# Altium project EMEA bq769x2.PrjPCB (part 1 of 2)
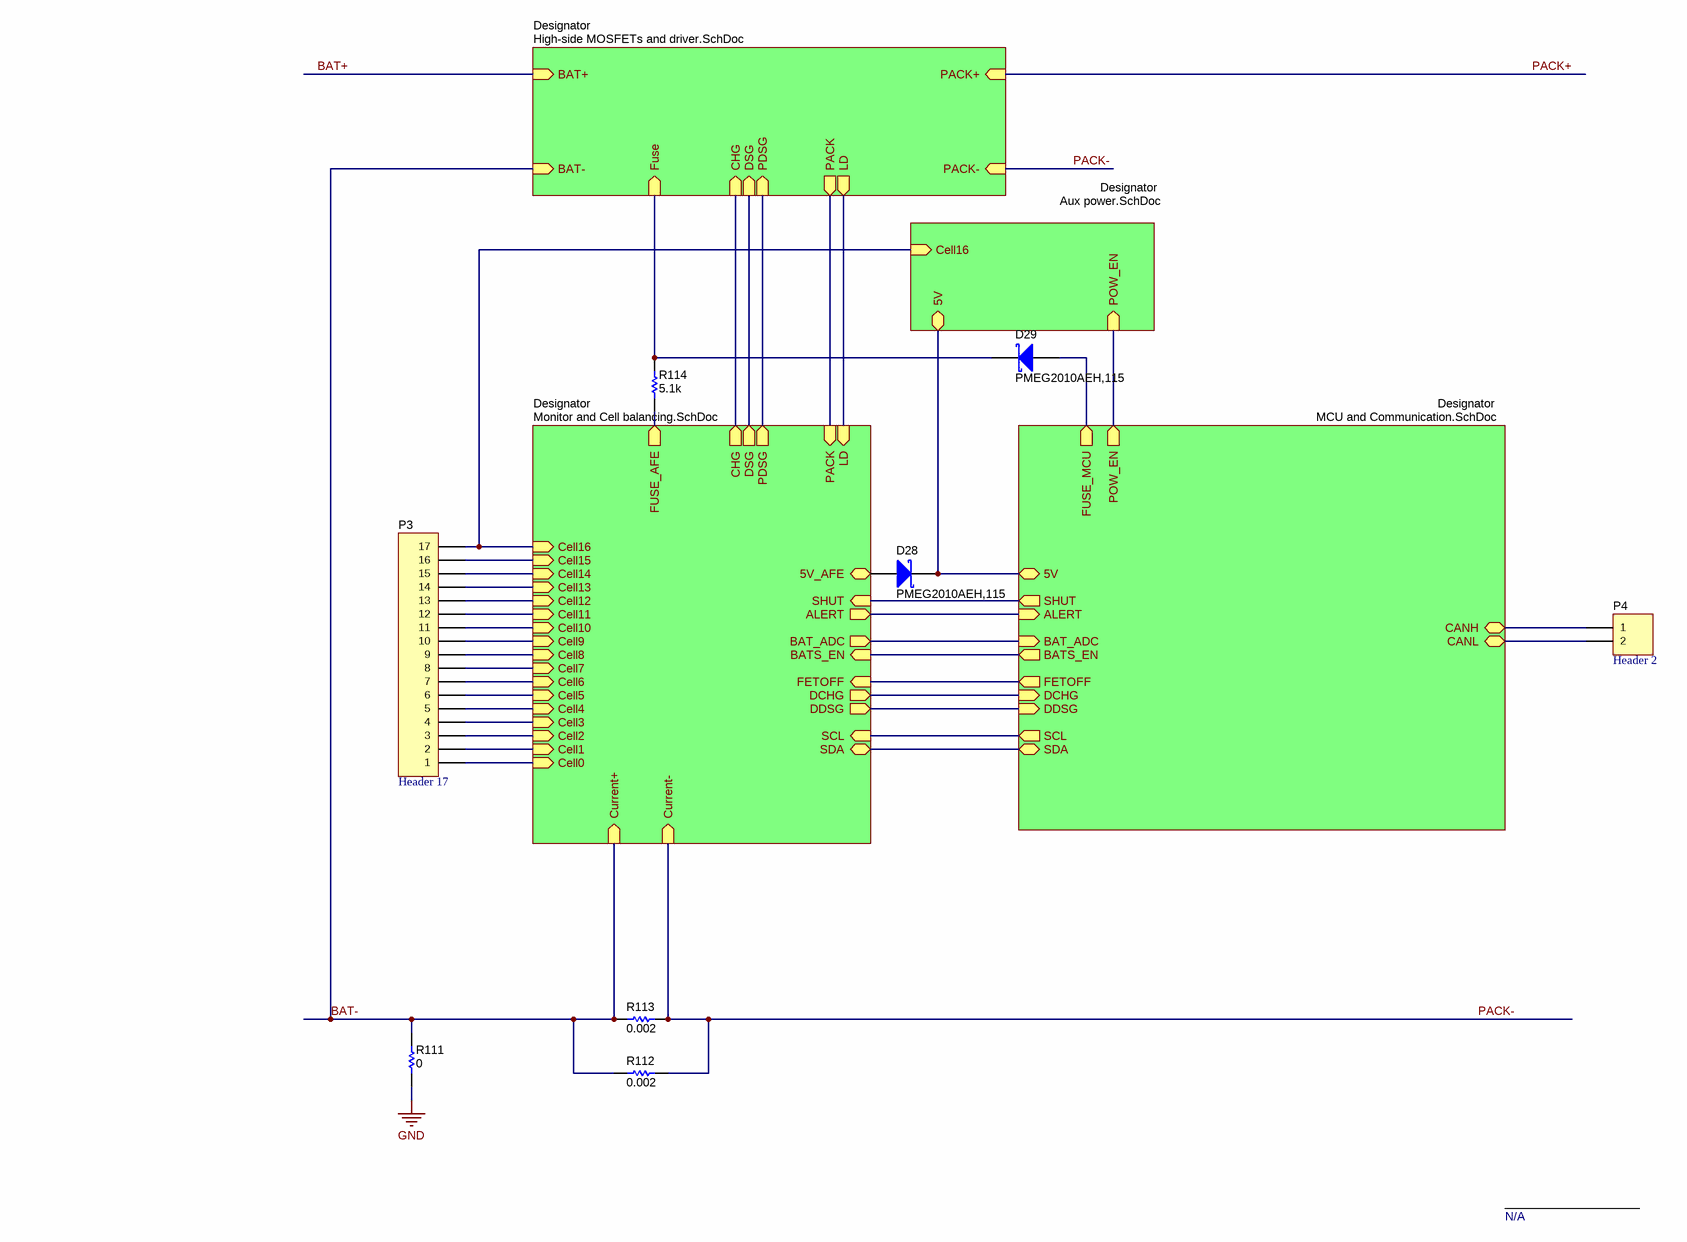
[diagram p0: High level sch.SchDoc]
TID: TIDA-010208; TechSupport: http://www.ti.com/support; SCH_Rev: E1; PRJ_Title: 10s-16s Battery Pack reference design; PRJ_Number: TIDA-010208; PRJ_Engineer: Ryan Tan; PRJ_Customer: Public Release; PCB_Rev: E1; PCB_Layout: Ryan Tan; CopyrightYear: 2017
7 sheets, 308 parts. Net scope: hierarchical (ports join the sheet entries above them; power ports are global).
Board file: v1.PcbDoc
Sheets:
  High level sch.SchDoc
    Designator = Monitor and Cell balancing.SchDoc
    Designator = Aux power.SchDoc
    Designator = MCU and Communication.SchDoc
    Designator = High-side MOSFETs and driver.SchDoc
    Designator = EVM_Hardware.SchDoc
    Designator = CoverSheet.SchDoc

## Sheet High level sch.SchDoc
size 431 x 279 mm; Date: Not shown in title block; ApprovedBy: Not shown in title block; CheckedBy: Not shown in title block; Author: Not shown in title block; CompanyName: Not shown in title block; Engineer: Not shown in title block; Organization: Not shown in title block; Address1: Not shown in title block; Address2: Not shown in title block; Address3: Not shown in title block; Address4: Not shown in title block; DocumentNumber: 1; Revision: Use project parameter SCH_Rev; SheetNumber: 2; SheetTotal: 7; PageSetup: Record=PageOptions¦CenterHorizontal=True¦CenterVertical=True¦PrintScale=1.00¦XCorrection=1.00¦YCorrection=1.00¦PrintKind=0¦BorderSize=5000000¦LeftOffset=0¦BottomOffset=0¦Orientation=2¦PaperLength=1000¦PaperWidth=1000¦Scale=100¦PaperSource=15¦PrintQuality=600¦MediaType=1¦DitherType=10¦PaperKind=Letter¦PrintScaleMode=1

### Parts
D28  PMEG2010AEH,115  [SOD-123F]
D29  PMEG2010AEH,115  [SOD-123F]
P3  Header 17  [HDR1X17]
P4  Header 2  [HDR1X2]
R111  ValueDisplayed: 0  [0603]  (hidden comment: CRCW06030000Z0EA)
R112  ValueDisplayed: 0.002  [2512]  (hidden comment: CSNL2512FT2L00)
R113  ValueDisplayed: 0.002  [2512]  (hidden comment: CSNL2512FT2L00)
R114  ValueDisplayed: 5.1k  [0603]  (hidden comment: CRCW06035K10JNEA)

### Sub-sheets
Designator = Monitor and Cell balancing.SchDoc: SHUT (in), ALERT (out), DDSG (out), DSG (out), DCHG (out), SCL (in), PDSG (out), Cell9 (in), SDA (bidir), CHG (out), Cell4 (in), Cell3 (in), Cell5 (in), Current+ (in), Current- (in), Cell8 (in), Cell12 (in), Cell6 (in), Cell7 (in), Cell10 (in), Cell11 (in), Cell2 (in), Cell1 (in), Cell15 (in), Cell16 (in), Cell0 (in), Cell13 (in), Cell14 (in), FETOFF (in), PACK (in), LD (in), 5V_AFE, FUSE_AFE (out), BAT_ADC (out), BATS_EN (in)
Designator = Aux power.SchDoc: POW_EN (in), 5V, Cell16 (in)
Designator = MCU and Communication.SchDoc: SDA (bidir), SCL (out), CANL (bidir), CANH (bidir), ALERT (in), POW_EN (out), DDSG (in), DCHG (in), SHUT (out), FETOFF (out), 5V, FUSE_MCU (out), BAT_ADC (in), BATS_EN (out)
Designator = High-side MOSFETs and driver.SchDoc: PACK- (in), CHG (in), DSG (in), Fuse (in), PACK+ (in), BAT+ (in), PACK (out), LD (out), PDSG (in), BAT- (in)
Designator = EVM_Hardware.SchDoc: no entries
Designator = CoverSheet.SchDoc: no entries

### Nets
GND: R111.1
5V: D28.1(K) ; sheet Designator/5V, sheet Designator/5V
5V_AFE: D28.2(A) ; sheet Designator/5V_AFE
ALERT: sheet Designator/ALERT, sheet Designator/ALERT
BAT-: R111.2 R112.1 R113.1 ; sheet Designator/Current+, sheet Designator/BAT-
BAT_ADC: sheet Designator/BAT_ADC, sheet Designator/BAT_ADC
BATS_EN: sheet Designator/BATS_EN, sheet Designator/BATS_EN
CANH: P4.1 ; sheet Designator/CANH
CANL: P4.2 ; sheet Designator/CANL
Cell0: P3.1 ; sheet Designator/Cell0
Cell1: P3.2 ; sheet Designator/Cell1
Cell2: P3.3 ; sheet Designator/Cell2
Cell3: P3.4 ; sheet Designator/Cell3
Cell4: P3.5 ; sheet Designator/Cell4
Cell5: P3.6 ; sheet Designator/Cell5
Cell6: P3.7 ; sheet Designator/Cell6
Cell7: P3.8 ; sheet Designator/Cell7
Cell8: P3.9 ; sheet Designator/Cell8
Cell9: P3.10 ; sheet Designator/Cell9
Cell10: P3.11 ; sheet Designator/Cell10
Cell11: P3.12 ; sheet Designator/Cell11
Cell12: P3.13 ; sheet Designator/Cell12
Cell13: P3.14 ; sheet Designator/Cell13
Cell14: P3.15 ; sheet Designator/Cell14
Cell15: P3.16 ; sheet Designator/Cell15
Cell16: P3.17 ; sheet Designator/Cell16, sheet Designator/Cell16
CHG: sheet Designator/CHG, sheet Designator/CHG
DCHG: sheet Designator/DCHG, sheet Designator/DCHG
DDSG: sheet Designator/DDSG, sheet Designator/DDSG
DSG: sheet Designator/DSG, sheet Designator/DSG
FETOFF: sheet Designator/FETOFF, sheet Designator/FETOFF
Fuse: D29.1(K) R114.2 ; sheet Designator/Fuse
FUSE_AFE: R114.1 ; sheet Designator/FUSE_AFE
FUSE_MCU: D29.2(A) ; sheet Designator/FUSE_MCU
LD: sheet Designator/LD, sheet Designator/LD
PACK: sheet Designator/PACK, sheet Designator/PACK
PACK-: R112.2 R113.2 ; sheet Designator/Current-, sheet Designator/PACK-
PDSG: sheet Designator/PDSG, sheet Designator/PDSG
POW_EN: sheet Designator/POW_EN, sheet Designator/POW_EN
SCL: sheet Designator/SCL, sheet Designator/SCL
SDA: sheet Designator/SDA, sheet Designator/SDA
SHUT: sheet Designator/SHUT, sheet Designator/SHUT

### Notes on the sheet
- N/A

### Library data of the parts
D28 D29 = PMEG2010AEH,115: Diode, Schottky, 20 V, 1 A, SOD-123F; Manufacturer: Nexperia; U/M: EA; Vf_V: 0.43; Value: 20V; Value1: 1A; Value2: 0.43V; Io_A: 1; Vr_V: 20; TJmax_C: 150; SizeAreaWB_mm2: 11.7; SizeArea_mm2: 5.6; SizeX_mm: 3.5; SizeY_mm: 1.6; SizeZ_mm: 1.1; AEC Category: Q101; Green_Lifecycle: Not Set; Green_REACh: Incomplete
P3 = Header 17: Header, 17-Pin
P4 = Header 2: Header, 2-Pin
R111 = CRCW06030000Z0EA: RES, 0, 5%, 0.1 W, 0603; Manufacturer: Vishay-Dale; CompType: Resistor; Value: 0; Value_Code: 0000; Tolerance_%: 5; Power_W: 0.1; Value2: 0.1W; VDC_V: 75; TempCo: 200 ppm/C; SizeArea_mm2: 1.28; SizeX_mm: 1.6; SizeY_mm: 0.8; SizeZ_mm: 1; EIA_Code: E24; U/M: EA; AEC Category: Q200; Green_Lifecycle: Active; Green_REACh: Passed
R112 R113 = CSNL2512FT2L00: RES, 0.002, 1%, 2 W, 2512; Manufacturer: Stackpole Electronics Inc; CompType: Resistor; Value: 0.002; Value_Code: 2L000; Tolerance_%: 1; Power_W: 2; Value2: 2W; VDC_V: 200; TempCo: 50 ppm/C; SizeArea_mm2: 20.16; SizeX_mm: 6.3; SizeY_mm: 3.2; SizeZ_mm: 0.71; U/M: EA; AEC Category: Q200
R114 = CRCW06035K10JNEA: RES, 5.1 k, 5%, 0.1 W, 0603; Manufacturer: Vishay-Dale; CompType: Resistor; Value: 5.1k; Res_ohm: 5100; Value_Code: 5k10; Tolerance_%: 5; Power_W: 0.1; Value2: 0.1W; VDC_V: 75; TempCo: 200 ppm/C; SizeArea_mm2: 1.28; SizeX_mm: 1.6; SizeY_mm: 0.8; SizeZ_mm: 1; EIA_Code: E24; U/M: EA; AEC Category: Q200; Green_Lifecycle: Active; Green_REACh: Passed

## Sheet Monitor and Cell balancing.SchDoc
size 431 x 279 mm; Date: Not shown in title block; ApprovedBy: Not shown in title block; CheckedBy: Not shown in title block; Author: Not shown in title block; CompanyName: Not shown in title block; Engineer: Not shown in title block; Organization: Not shown in title block; Address1: Not shown in title block; Address2: Not shown in title block; Address3: Not shown in title block; Address4: Not shown in title block; DocumentNumber: 1; Revision: Use project parameter SCH_Rev; SheetNumber: 3; SheetTotal: 7; PageSetup: Record=PageOptions¦CenterHorizontal=True¦CenterVertical=True¦PrintScale=1.00¦XCorrection=1.00¦YCorrection=1.00¦PrintKind=0¦BorderSize=5000000¦LeftOffset=0¦BottomOffset=0¦Orientation=2¦PaperLength=1000¦PaperWidth=1000¦Scale=100¦PaperSource=15¦PrintQuality=600¦MediaType=1¦DitherType=10¦PaperKind=Letter¦PrintScaleMode=1
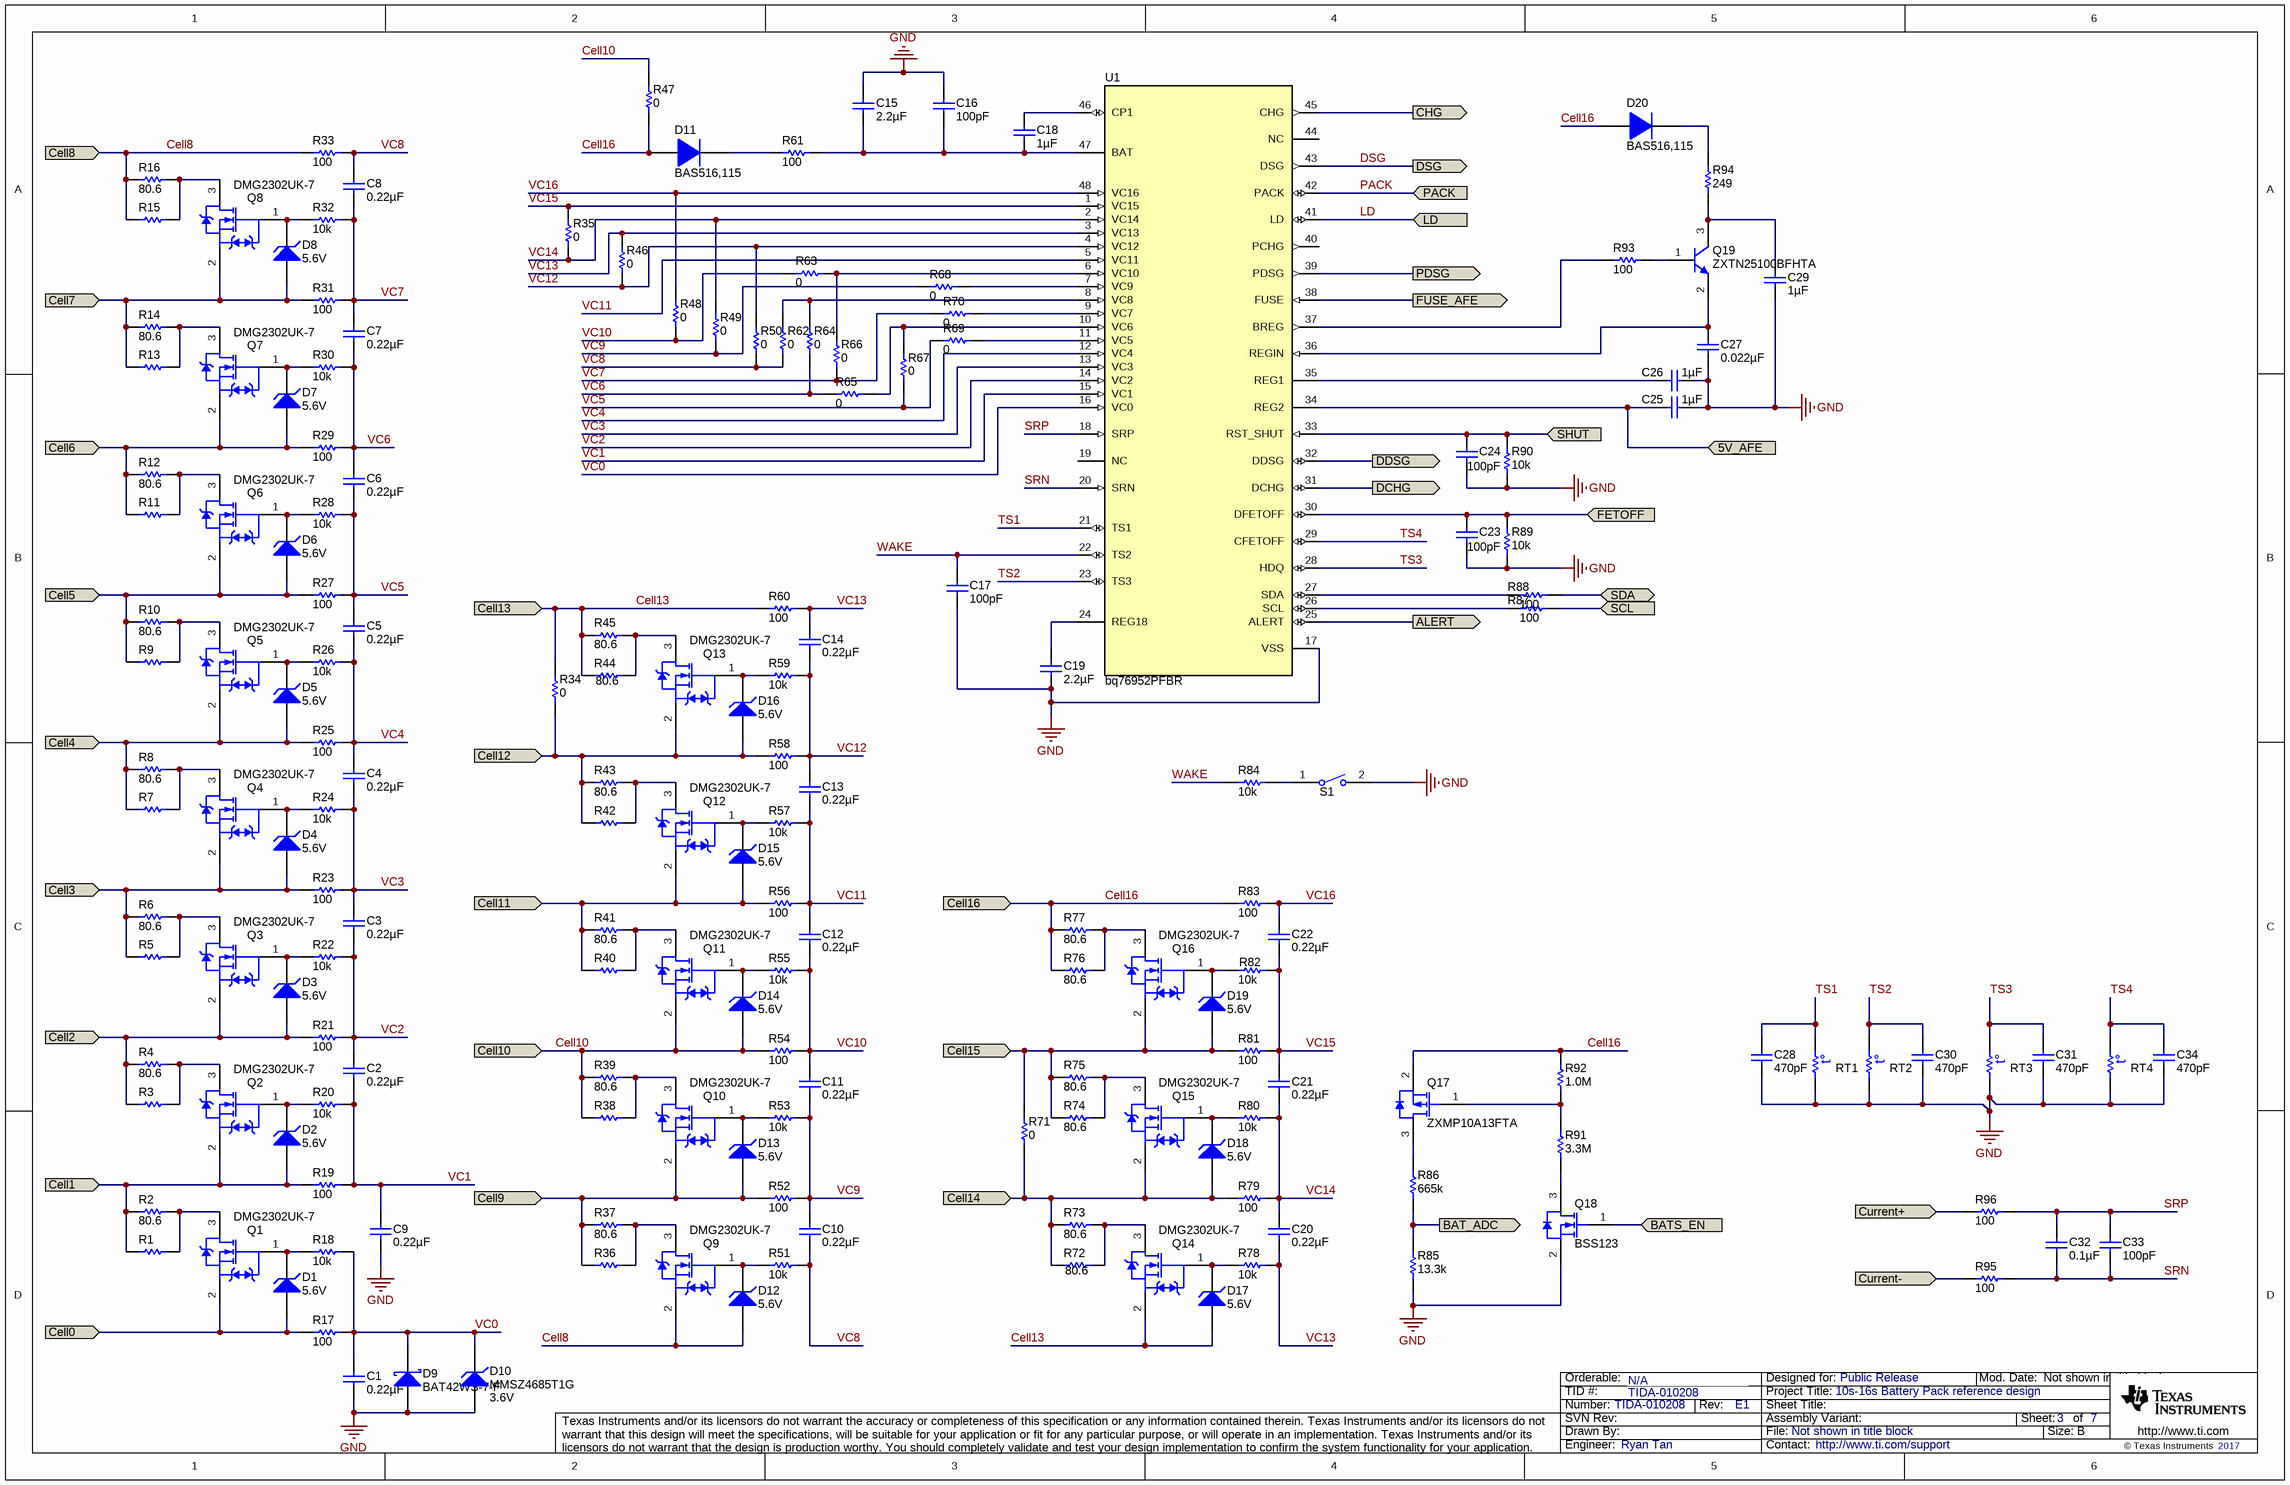
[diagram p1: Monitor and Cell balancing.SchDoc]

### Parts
C1  ValueDisplayed: 0.22µF  [0603]  (hidden comment: GCM188R71H224KA64D)
C2  ValueDisplayed: 0.22µF  [0603]  (hidden comment: GCM188R71H224KA64D)
C3  ValueDisplayed: 0.22µF  [0603]  (hidden comment: GCM188R71H224KA64D)
C4  ValueDisplayed: 0.22µF  [0603]  (hidden comment: GCM188R71H224KA64D)
C5  ValueDisplayed: 0.22µF  [0603]  (hidden comment: GCM188R71H224KA64D)
C6  ValueDisplayed: 0.22µF  [0603]  (hidden comment: GCM188R71H224KA64D)
C7  ValueDisplayed: 0.22µF  [0603]  (hidden comment: GCM188R71H224KA64D)
C8  ValueDisplayed: 0.22µF  [0603]  (hidden comment: GCM188R71H224KA64D)
C9  ValueDisplayed: 0.22µF  [0603]  (hidden comment: GCM188R71H224KA64D)
C10  ValueDisplayed: 0.22µF  [0603]  (hidden comment: GCM188R71H224KA64D)
C11  ValueDisplayed: 0.22µF  [0603]  (hidden comment: GCM188R71H224KA64D)
C12  ValueDisplayed: 0.22µF  [0603]  (hidden comment: GCM188R71H224KA64D)
C13  ValueDisplayed: 0.22µF  [0603]  (hidden comment: GCM188R71H224KA64D)
C14  ValueDisplayed: 0.22µF  [0603]  (hidden comment: GCM188R71H224KA64D)
C15  ValueDisplayed: 2.2µF  [1206_190]  (hidden comment: CL31B225KCHSNNE)
C16  ValueDisplayed: 100pF  [0603]  (hidden comment: GRM1885C2A101JA01D)
C17  ValueDisplayed: 100pF  [0603]  (hidden comment: GRM1885C2A101JA01D)
C18  ValueDisplayed: 1µF  [0603]  (hidden comment: C1608X7R1E105K080AB)
C19  ValueDisplayed: 2.2µF  [0603]  (hidden comment: EMK107BB7225MA-T)
C20  ValueDisplayed: 0.22µF  [0603]  (hidden comment: GCM188R71H224KA64D)
C21  ValueDisplayed: 0.22µF  [0603]  (hidden comment: GCM188R71H224KA64D)
C22  ValueDisplayed: 0.22µF  [0603]  (hidden comment: GCM188R71H224KA64D)
C23  ValueDisplayed: 100pF  [0603]  (hidden comment: GRM1885C2A101JA01D)
C24  ValueDisplayed: 100pF  [0603]  (hidden comment: GRM1885C2A101JA01D)
C25  ValueDisplayed: 1µF  [0603]  (hidden comment: GCM188R71C105KA64D)
C26  ValueDisplayed: 1µF  [0603]  (hidden comment: GCM188R71C105KA64D)
C27  ValueDisplayed: 0.022µF  [0603]  (hidden comment: GRM188R71H223KA01D)
C28  ValueDisplayed: 470pF  [0603]  (hidden comment: GRM188R71H471KA01D)
C29  ValueDisplayed: 1µF  [1206_180]  (hidden comment: C3216X7R2A105K160AA)
C30  ValueDisplayed: 470pF  [0603]  (hidden comment: GRM188R71H471KA01D)
C31  ValueDisplayed: 470pF  [0603]  (hidden comment: GRM188R71H471KA01D)
C32  ValueDisplayed: 0.1µF  [0603]  (hidden comment: GRM188R71H104KA93D)
C33  ValueDisplayed: 100pF  [0603]  (hidden comment: GRM1885C2A101JA01D)
C34  ValueDisplayed: 470pF  [0603]  (hidden comment: GRM188R71H471KA01D)
D1  value 5.6V  [SOD-523]  (hidden comment: BZT52C5V6T-7)
D2  value 5.6V  [SOD-523]  (hidden comment: BZT52C5V6T-7)
D3  value 5.6V  [SOD-523]  (hidden comment: BZT52C5V6T-7)
D4  value 5.6V  [SOD-523]  (hidden comment: BZT52C5V6T-7)
D5  value 5.6V  [SOD-523]  (hidden comment: BZT52C5V6T-7)
D6  value 5.6V  [SOD-523]  (hidden comment: BZT52C5V6T-7)
D7  value 5.6V  [SOD-523]  (hidden comment: BZT52C5V6T-7)
D8  value 5.6V  [SOD-523]  (hidden comment: BZT52C5V6T-7)
D9  BAT42WS-7-F  [SOD-323]
D10  MMSZ4685T1G  value 3.6V  [SOD-123]
D11  BAS516,115  [SOD-523]
D12  value 5.6V  [SOD-523]  (hidden comment: BZT52C5V6T-7)
D13  value 5.6V  [SOD-523]  (hidden comment: BZT52C5V6T-7)
D14  value 5.6V  [SOD-523]  (hidden comment: BZT52C5V6T-7)
D15  value 5.6V  [SOD-523]  (hidden comment: BZT52C5V6T-7)
D16  value 5.6V  [SOD-523]  (hidden comment: BZT52C5V6T-7)
D17  value 5.6V  [SOD-523]  (hidden comment: BZT52C5V6T-7)
D18  value 5.6V  [SOD-523]  (hidden comment: BZT52C5V6T-7)
D19  value 5.6V  [SOD-523]  (hidden comment: BZT52C5V6T-7)
D20  BAS516,115  [SOD-523]
Q1  DMG2302UK-7  [SOT-23]
Q2  DMG2302UK-7  [SOT-23]
Q3  DMG2302UK-7  [SOT-23]
Q4  DMG2302UK-7  [SOT-23]
Q5  DMG2302UK-7  [SOT-23]
Q6  DMG2302UK-7  [SOT-23]
Q7  DMG2302UK-7  [SOT-23]
Q8  DMG2302UK-7  [SOT-23]
Q9  DMG2302UK-7  [SOT-23]
Q10  DMG2302UK-7  [SOT-23]
Q11  DMG2302UK-7  [SOT-23]
Q12  DMG2302UK-7  [SOT-23]
Q13  DMG2302UK-7  [SOT-23]
Q14  DMG2302UK-7  [SOT-23]
Q15  DMG2302UK-7  [SOT-23]
Q16  DMG2302UK-7  [SOT-23]
Q17  ZXMP10A13FTA  [SOT-23]
Q18  BSS123  [SOT-23]
Q19  ZXTN25100BFHTA  [SOT-23]
R1  CRCW120680R6FKEA  [1206]  (value not drawn)
R2  ValueDisplayed: 80.6  [1206]  (hidden comment: CRCW120680R6FKEA)
R3  CRCW120680R6FKEA  [1206]  (value not drawn)
R4  ValueDisplayed: 80.6  [1206]  (hidden comment: CRCW120680R6FKEA)
R5  CRCW120680R6FKEA  [1206]  (value not drawn)
R6  ValueDisplayed: 80.6  [1206]  (hidden comment: CRCW120680R6FKEA)
R7  CRCW120680R6FKEA  [1206]  (value not drawn)
R8  ValueDisplayed: 80.6  [1206]  (hidden comment: CRCW120680R6FKEA)
R9  CRCW120680R6FKEA  [1206]  (value not drawn)
R10  ValueDisplayed: 80.6  [1206]  (hidden comment: CRCW120680R6FKEA)
R11  CRCW120680R6FKEA  [1206]  (value not drawn)
R12  ValueDisplayed: 80.6  [1206]  (hidden comment: CRCW120680R6FKEA)
R13  CRCW120680R6FKEA  [1206]  (value not drawn)
R14  ValueDisplayed: 80.6  [1206]  (hidden comment: CRCW120680R6FKEA)
R15  CRCW120680R6FKEA  [1206]  (value not drawn)
R16  ValueDisplayed: 80.6  [1206]  (hidden comment: CRCW120680R6FKEA)
R17  ValueDisplayed: 100  [0603]  (hidden comment: CRCW0603100RFKEA)
R18  ValueDisplayed: 10k  [0603]  (hidden comment: CRCW060310K0JNEA)
R19  ValueDisplayed: 100  [0603]  (hidden comment: CRCW0603100RFKEA)
R20  ValueDisplayed: 10k  [0603]  (hidden comment: CRCW060310K0JNEA)
R21  ValueDisplayed: 100  [0603]  (hidden comment: CRCW0603100RFKEA)
R22  ValueDisplayed: 10k  [0603]  (hidden comment: CRCW060310K0JNEA)
R23  ValueDisplayed: 100  [0603]  (hidden comment: CRCW0603100RFKEA)
R24  ValueDisplayed: 10k  [0603]  (hidden comment: CRCW060310K0JNEA)
R25  ValueDisplayed: 100  [0603]  (hidden comment: CRCW0603100RFKEA)
R26  ValueDisplayed: 10k  [0603]  (hidden comment: CRCW060310K0JNEA)
R27  ValueDisplayed: 100  [0603]  (hidden comment: CRCW0603100RFKEA)
R28  ValueDisplayed: 10k  [0603]  (hidden comment: CRCW060310K0JNEA)
R29  ValueDisplayed: 100  [0603]  (hidden comment: CRCW0603100RFKEA)
R30  ValueDisplayed: 10k  [0603]  (hidden comment: CRCW060310K0JNEA)
R31  ValueDisplayed: 100  [0603]  (hidden comment: CRCW0603100RFKEA)
R32  ValueDisplayed: 10k  [0603]  (hidden comment: CRCW060310K0JNEA)
R33  ValueDisplayed: 100  [0603]  (hidden comment: CRCW0603100RFKEA)
R34  ValueDisplayed: 0  [0402]  (hidden comment: CRCW04020000Z0ED)
R35  ValueDisplayed: 0  [0603]  (hidden comment: CRCW06030000Z0EA)
R36  CRCW120680R6FKEA  [1206]  (value not drawn)
R37  ValueDisplayed: 80.6  [1206]  (hidden comment: CRCW120680R6FKEA)
R38  CRCW120680R6FKEA  [1206]  (value not drawn)
R39  ValueDisplayed: 80.6  [1206]  (hidden comment: CRCW120680R6FKEA)
R40  CRCW120680R6FKEA  [1206]  (value not drawn)
R41  ValueDisplayed: 80.6  [1206]  (hidden comment: CRCW120680R6FKEA)
R42  CRCW120680R6FKEA  [1206]  (value not drawn)
R43  ValueDisplayed: 80.6  [1206]  (hidden comment: CRCW120680R6FKEA)
R44  value 80.6  [1206]  (hidden comment: CRCW120680R6FKEA)
R45  ValueDisplayed: 80.6  [1206]  (hidden comment: CRCW120680R6FKEA)
R46  ValueDisplayed: 0  [0402]  (hidden comment: CRCW04020000Z0ED)
R47  ValueDisplayed: 0  [0402]  (hidden comment: CRCW04020000Z0ED)
R48  ValueDisplayed: 0  [0603]  (hidden comment: CRCW06030000Z0EA)
R49  ValueDisplayed: 0  [0603]  (hidden comment: CRCW06030000Z0EA)
R50  ValueDisplayed: 0  [0603]  (hidden comment: CRCW06030000Z0EA)
R51  ValueDisplayed: 10k  [0603]  (hidden comment: CRCW060310K0JNEA)
R52  ValueDisplayed: 100  [0603]  (hidden comment: CRCW0603100RFKEA)
R53  ValueDisplayed: 10k  [0603]  (hidden comment: CRCW060310K0JNEA)
R54  ValueDisplayed: 100  [0603]  (hidden comment: CRCW0603100RFKEA)
R55  ValueDisplayed: 10k  [0603]  (hidden comment: CRCW060310K0JNEA)
R56  ValueDisplayed: 100  [0603]  (hidden comment: CRCW0603100RFKEA)
R57  ValueDisplayed: 10k  [0603]  (hidden comment: CRCW060310K0JNEA)
R58  ValueDisplayed: 100  [0603]  (hidden comment: CRCW0603100RFKEA)
R59  ValueDisplayed: 10k  [0603]  (hidden comment: CRCW060310K0JNEA)
R60  ValueDisplayed: 100  [0603]  (hidden comment: CRCW0603100RFKEA)
R61  ValueDisplayed: 100  [0603]  (hidden comment: CRCW0603100RFKEA)
R62  ValueDisplayed: 0  [0603]  (hidden comment: CRCW06030000Z0EA)
R63  ValueDisplayed: 0  [0603]  (hidden comment: CRCW06030000Z0EA)
R64  ValueDisplayed: 0  [0603]  (hidden comment: CRCW06030000Z0EA)
R65  ValueDisplayed: 0  [0603]  (hidden comment: CRCW06030000Z0EA)
R66  ValueDisplayed: 0  [0603]  (hidden comment: CRCW06030000Z0EA)
R67  ValueDisplayed: 0  [0603]  (hidden comment: CRCW06030000Z0EA)
R68  ValueDisplayed: 0  [0603]  (hidden comment: CRCW06030000Z0EA)
R69  ValueDisplayed: 0  [0603]  (hidden comment: CRCW06030000Z0EA)
R70  ValueDisplayed: 0  [0603]  (hidden comment: CRCW06030000Z0EA)
R71  ValueDisplayed: 0  [0402]  (hidden comment: CRCW04020000Z0ED)
R72  ValueDisplayed: 80.6  [1206]  (hidden comment: CRCW120680R6FKEA)
R73  ValueDisplayed: 80.6  [1206]  (hidden comment: CRCW120680R6FKEA)
R74  ValueDisplayed: 80.6  [1206]  (hidden comment: CRCW120680R6FKEA)
R75  ValueDisplayed: 80.6  [1206]  (hidden comment: CRCW120680R6FKEA)
R76  ValueDisplayed: 80.6  [1206]  (hidden comment: CRCW120680R6FKEA)
R77  ValueDisplayed: 80.6  [1206]  (hidden comment: CRCW120680R6FKEA)
R78  ValueDisplayed: 10k  [0603]  (hidden comment: CRCW060310K0JNEA)
R79  ValueDisplayed: 100  [0603]  (hidden comment: CRCW0603100RFKEA)
R80  ValueDisplayed: 10k  [0603]  (hidden comment: CRCW060310K0JNEA)
R81  ValueDisplayed: 100  [0603]  (hidden comment: CRCW0603100RFKEA)
R82  ValueDisplayed: 10k  [0603]  (hidden comment: CRCW060310K0JNEA)
R83  ValueDisplayed: 100  [0603]  (hidden comment: CRCW0603100RFKEA)
R84  ValueDisplayed: 10k  [0603]  (hidden comment: CRCW060310K0JNEA)
R85  ValueDisplayed: 13.3k  [0603]  (hidden comment: RT0603DRE0713K3L)
R86  ValueDisplayed: 665k  [0603]  (hidden comment: RT0603DRE07665KL)
R87  ValueDisplayed: 100  [0603]  (hidden comment: CRCW0603100RFKEA)
R88  ValueDisplayed: 100  [0603]  (hidden comment: CRCW0603100RFKEA)
R89  ValueDisplayed: 10k  [0603]  (hidden comment: CRCW060310K0JNEA)
R90  ValueDisplayed: 10k  [0603]  (hidden comment: CRCW060310K0JNEA)
R91  ValueDisplayed: 3.3M  [0603]  (hidden comment: CRCW06033M30JNEA)
R92  ValueDisplayed: 1.0M  [0603]  (hidden comment: CRCW06031M00JNEA)
R93  ValueDisplayed: 100  [0603]  (hidden comment: CRCW0603100RFKEA)
R94  ValueDisplayed: 249  [0603]  (hidden comment: RC0603FR-07249RL)
R95  ValueDisplayed: 100  [0603]  (hidden comment: CRCW0603100RFKEA)
R96  ValueDisplayed: 100  [0603]  (hidden comment: CRCW0603100RFKEA)
RT1  MF51E103F3950  [Thermistor_103AT-2]  (value not drawn)
RT2  MF51E103F3950  [Thermistor_103AT-2]  (value not drawn)
RT3  MF51E103F3950  [Thermistor_103AT-2]  (value not drawn)
RT4  MF51E103F3950  [Thermistor_103AT-2]  (value not drawn)
S1  RS-032G05A3-SM RT  [SW_RS-032G05A3-SM]  (value not drawn)
U1  bq76952PFBR  [PFB0048A_N]

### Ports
5V_AFE, ALERT (out), BAT_ADC (out), BATS_EN (in), Cell0 (in), Cell1 (in), Cell2 (in), Cell3 (in), Cell4 (in), Cell5 (in), Cell6 (in), Cell7 (in), Cell8 (in), Cell9 (in), Cell10 (in), Cell11 (in), Cell12 (in), Cell13 (in), Cell14 (in), Cell15 (in), Cell16 (in), CHG (out), Current+ (in), Current- (in), DCHG (out), DDSG (out), DSG (out), FETOFF (in), FUSE_AFE (out), LD (in), PACK (in), PDSG (out), SCL (in), SDA (bidir), SHUT (in)

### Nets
GND: C1.2 C9.2 C15.1 C16.1 C17.2 C19.2 C23.2 C24.2 C25.2 C26.2 C27.2 C28.2 C29.2 C30.2 C31.2 C34.2 D9.2(A) D10.2(A) Q18.2(S) R85.1 R89.1 R90.1 RT1.1 RT2.1 RT3.1 RT4.1 S1.2 U1.17(VSS)
5V_AFE: C25.1 U1.34(REG2) ; port 5V_AFE
ALERT: U1.25(ALERT) ; port ALERT
BAT-: R96.1 ; port Current+
BAT_ADC: R85.2 R86.1 ; port BAT_ADC
BATS_EN: Q18.1(G) ; port BATS_EN
Cell0: D1.2(A) Q1.2(S) R17.1 ; port Cell0
Cell1: D2.2(A) Q2.2(S) R1.1 R2.1 R19.1 ; port Cell1
Cell2: D3.2(A) Q3.2(S) R3.1 R4.1 R21.1 ; port Cell2
Cell3: D4.2(A) Q4.2(S) R5.1 R6.1 R23.1 ; port Cell3
Cell4: D5.2(A) Q5.2(S) R7.1 R8.1 R25.1 ; port Cell4
Cell5: D6.2(A) Q6.2(S) R9.1 R10.1 R27.1 ; port Cell5
Cell6: D7.2(A) Q7.2(S) R11.1 R12.1 R29.1 ; port Cell6
Cell7: D8.2(A) Q8.2(S) R13.1 R14.1 R31.1 ; port Cell7
Cell8: D12.2(A) Q9.2(S) R15.1 R16.1 R33.1 ; port Cell8
Cell9: D13.2(A) Q10.2(S) R36.1 R37.1 R52.1 ; port Cell9
Cell10: D14.2(A) Q11.2(S) R38.1 R39.1 R47.2 R54.1 ; port Cell10
Cell11: D15.2(A) Q12.2(S) R40.1 R41.1 R56.1 ; port Cell11
Cell12: D16.2(A) Q13.2(S) R34.1 R42.1 R43.1 R58.1 ; port Cell12
Cell13: D17.2(A) Q14.2(S) R34.2 R44.1 R45.1 R60.1 ; port Cell13
Cell14: D18.2(A) Q15.2(S) R71.1 R72.1 R73.1 R79.1 ; port Cell14
Cell15: D19.2(A) Q16.2(S) R71.2 R74.1 R75.1 R81.1 ; port Cell15
Cell16: D11.2(A) D20.2(A) Q17.2(S) R47.1 R76.1 R77.1 R83.1 R92.2 ; port Cell16
CHG: U1.45(CHG) ; port CHG
DCHG: U1.31(DCHG) ; port DCHG
DDSG: U1.32(DDSG) ; port DDSG
DSG: U1.43(DSG) ; port DSG
FETOFF: C23.1 R89.2 U1.30(DFETOFF) ; port FETOFF
FUSE_AFE: U1.38(FUSE) ; port FUSE_AFE
LD: U1.41(LD) ; port LD
PACK: U1.42(PACK) ; port PACK
PACK-: R95.1 ; port Current-
PDSG: U1.39(PDSG) ; port PDSG
SCL: R87.1 ; port SCL
SDA: R88.1 ; port SDA
SHUT: C24.1 R90.2 U1.33(RST_SHUT) ; port SHUT
SRN: C32.2 C33.2 R95.2 U1.20(SRN)
SRP: C32.1 C33.1 R96.2 U1.18(SRP)
TS1: C28.1 RT1.2 U1.21(TS1)
TS2: C30.1 RT2.2 U1.23(TS3)
TS3: C31.1 RT3.2 U1.28(HDQ)
TS4: C34.1 RT4.2 U1.29(CFETOFF)
VC0: C1.1 D9.1(K) D10.1(K) R17.2 R18.2 U1.16(VC0)
VC1: C2.2 C9.1 R19.2 R20.2 U1.15(VC1)
VC2: C2.1 C3.2 R21.2 R22.2 U1.14(VC2)
VC3: C3.1 C4.2 R23.2 R24.2 U1.13(VC3)
VC4: C4.1 C5.2 R25.2 R26.2 U1.12(VC4)
VC5: C5.1 C6.2 R27.2 R28.2 R67.1 R69.2
VC6: C6.1 C7.2 R29.2 R30.2 R64.1 R65.2
VC7: C7.1 C8.2 R31.2 R32.2 R66.1 R70.2
VC8: C8.1 C10.2 R33.2 R50.1 R51.2 R62.1
VC9: C10.1 C11.2 R49.1 R52.2 R53.2 R68.2
VC10: C11.1 C12.2 R48.1 R54.2 R55.2 R63.1
VC11: C12.1 C13.2 R56.2 R57.2 U1.5(VC11)
VC12: C13.1 C14.2 R46.1 R50.2 R58.2 R59.2 U1.4(VC12)
VC13: C14.1 C20.2 R46.2 R60.2 R78.2 U1.3(VC13)
VC14: C20.1 C21.2 R35.2 R49.2 R79.2 R80.2 U1.2(VC14)
VC15: C21.1 C22.2 R35.1 R81.2 R82.2 U1.1(VC15)
VC16: C22.1 R48.2 R83.2 U1.48(VC16)
WAKE: C17.1 R84.2 U1.22(TS2)
NetC15_2: C15.2 C16.2 C18.2 R61.2 U1.47(BAT)
NetC18_1: C18.1 U1.46(CP1)
NetC19_1: C19.1 U1.24(REG18)
NetC26_1: C26.1 U1.35(REG1)
NetC27_1: C27.1 Q19.2(E) U1.36(REGIN)
NetC29_1: C29.1 Q19.3(C) R94.1
NetD1_1: D1.1(K) Q1.1(G) R18.1
NetD2_1: D2.1(K) Q2.1(G) R20.1
NetD3_1: D3.1(K) Q3.1(G) R22.1
NetD4_1: D4.1(K) Q4.1(G) R24.1
NetD5_1: D5.1(K) Q5.1(G) R26.1
NetD6_1: D6.1(K) Q6.1(G) R28.1
NetD7_1: D7.1(K) Q7.1(G) R30.1
NetD8_1: D8.1(K) Q8.1(G) R32.1
NetD11_1: D11.1(K) R61.1
NetD12_1: D12.1(K) Q9.1(G) R51.1
NetD13_1: D13.1(K) Q10.1(G) R53.1
NetD14_1: D14.1(K) Q11.1(G) R55.1
NetD15_1: D15.1(K) Q12.1(G) R57.1
NetD16_1: D16.1(K) Q13.1(G) R59.1
NetD17_1: D17.1(K) Q14.1(G) R78.1
NetD18_1: D18.1(K) Q15.1(G) R80.1
NetD19_1: D19.1(K) Q16.1(G) R82.1
NetD20_1: D20.1(K) R94.2
NetQ1_3: Q1.3(D) R1.2 R2.2
NetQ2_3: Q2.3(D) R3.2 R4.2
NetQ3_3: Q3.3(D) R5.2 R6.2
NetQ4_3: Q4.3(D) R7.2 R8.2
NetQ5_3: Q5.3(D) R9.2 R10.2
NetQ6_3: Q6.3(D) R11.2 R12.2
NetQ7_3: Q7.3(D) R13.2 R14.2
NetQ8_3: Q8.3(D) R15.2 R16.2
NetQ9_3: Q9.3(D) R36.2 R37.2
NetQ10_3: Q10.3(D) R38.2 R39.2
NetQ11_3: Q11.3(D) R40.2 R41.2
NetQ12_3: Q12.3(D) R42.2 R43.2
NetQ13_3: Q13.3(D) R44.2 R45.2
NetQ14_3: Q14.3(D) R72.2 R73.2
NetQ15_3: Q15.3(D) R74.2 R75.2
NetQ16_3: Q16.3(D) R76.2 R77.2
NetQ17_1: Q17.1(G) R91.2 R92.1
NetQ17_3: Q17.3(D) R86.2
NetQ18_3: Q18.3(D) R91.1
NetQ19_1: Q19.1(B) R93.2
NetR62_2: R62.2 R64.2 U1.8(VC8)
NetR63_2: R63.2 R66.2 U1.6(VC10)
NetR65_1: R65.1 R67.2 U1.10(VC6)
NetR68_1: R68.1 U1.7(VC9)
NetR69_1: R69.1 U1.11(VC5)
NetR70_1: R70.1 U1.9(VC7)
NetR84_1: R84.1 S1.1
NetR87_2: R87.2 U1.26(SCL)
NetR88_2: R88.2 U1.27(SDA)
NetR93_1: R93.1 U1.37(BREG)

Not connected (* = marked no-connect by the designer): U1 19(NC) 40(PCHG) 44(NC)

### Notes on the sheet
- N/A

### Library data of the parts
C1-C14 C20-C22 = GCM188R71H224KA64D: CAP, CERM, 0.22 µF, 50 V,+/- 10%, X7R, AEC-Q200 Grade 1, 0603; Manufacturer: MuRata; Polarized: N; CompType: Capacitor; Value: 0.22uF; U/M: EA; Cap_F: 0.00000022; Tolerance_%: 10; VDC_V: 50; Value2: 50V; TaMin_C: -55; TaMax_C: 125; SizeArea_mm2: 1.28; SizeAreaWB_mm2: 4.68; SizeX_mm: 1.6; SizeY_mm: 0.8; SizeZ_mm: 1; AEC Category: Q200; AEC Qualified: Y; Green_Lifecycle: Active; Green_REACh: Passed
C15 = CL31B225KCHSNNE: CAP, CERM, 2.2 µF, 100 V,+/- 10%, X7R, 1206; Manufacturer: Samsung Electro-Mechanics; Polarized: N; CompType: Capacitor; Value: 2.2uF; U/M: EA; Cap_F: 0.0000022; Tolerance_%: 10; VDC_V: 100; Value2: 100V; TaMin_C: -55; TaMax_C: 125; Cap_Case: 1206; SizeArea_mm2: 5.12; SizeAreaWB_mm2: 10.92; SizeX_mm: 3.2; SizeY_mm: 1.6; SizeZ_mm: 1.9; AEC Category: Q200; Green_Lifecycle: Active; Green_REACh: Passed
C16 C17 C23 C24 C33 = GRM1885C2A101JA01D: CAP, CERM, 100 pF, 100 V,+/- 5%, C0G/NP0, 0603; Manufacturer: MuRata; Polarized: N; CompType: Capacitor; Value: 100pF; U/M: EA; Cap_F: 0.0000000001; Tolerance_%: 5; VDC_V: 100; Value2: 100V; TaMin_C: -55; TaMax_C: 125; SizeArea_mm2: 1.28; SizeAreaWB_mm2: 4.68; SizeX_mm: 1.6; SizeY_mm: 0.8; SizeZ_mm: 1; AEC Category: Q200; Green_Lifecycle: Active; Green_REACh: Passed
C18 = C1608X7R1E105K080AB: CAP, CERM, 1 µF, 25 V,+/- 10%, X7R, 0603; Manufacturer: TDK; Polarized: N; CompType: Capacitor; Value: 1uF; U/M: EA; Cap_F: 0.000001; Tolerance_%: 10; VDC_V: 25; Value2: 25V; TaMin_C: -55; TaMax_C: 125; SizeArea_mm2: 1.28; SizeAreaWB_mm2: 4.68; SizeX_mm: 1.6; SizeY_mm: 0.8; SizeZ_mm: 1; AEC Category: Q200; Green_Lifecycle: Active; Green_REACh: Passed
C19 = EMK107BB7225MA-T: CAP, CERM, 2.2 µF, 16 V,+/- 10%, X7R, 0603; Manufacturer: Taiyo Yuden; Polarized: N; CompType: Capacitor; Value: 2.2uF; U/M: EA; Cap_F: 0.0000022; Tolerance_%: 10; VDC_V: 16; Value2: 16V; TaMin_C: -55; TaMax_C: 125; SizeArea_mm2: 1.28; SizeAreaWB_mm2: 4.68; SizeX_mm: 1.6; SizeY_mm: 0.8; SizeZ_mm: 1; AEC Category: Q200
C25 C26 = GCM188R71C105KA64D: CAP, CERM, 1 µF, 16 V,+/- 10%, X7R, AEC-Q200 Grade 1, 0603; Manufacturer: MuRata; Polarized: N; CompType: Capacitor; Value: 1uF; U/M: EA; Cap_F: 0.000001; Tolerance_%: 10; VDC_V: 16; Value2: 16V; TaMin_C: -55; TaMax_C: 125; SizeArea_mm2: 1.28; SizeAreaWB_mm2: 4.68; SizeX_mm: 1.6; SizeY_mm: 0.8; SizeZ_mm: 1; AEC Category: Q200; AEC Qualified: Y; Green_Lifecycle: Active; Green_REACh: Passed
C27 = GRM188R71H223KA01D: CAP, CERM, 0.022 µF, 50 V,+/- 10%, X7R, 0603; Manufacturer: MuRata; Polarized: N; CompType: Capacitor; Value: 0.022uF; U/M: EA; Cap_F: 0.000000022; Tolerance_%: 10; VDC_V: 50; Value2: 50V; TaMin_C: -55; TaMax_C: 125; SizeArea_mm2: 1.28; SizeAreaWB_mm2: 4.68; SizeX_mm: 1.6; SizeY_mm: 0.8; SizeZ_mm: 1; AEC Category: Q200; Green_Lifecycle: Active; Green_REACh: Passed
C28 C30 C31 C34 = GRM188R71H471KA01D: CAP, CERM, 470 pF, 50 V,+/- 10%, X7R, 0603; Manufacturer: MuRata; Polarized: N; CompType: Capacitor; Value: 470pF; U/M: EA; Cap_F: 0.00000000047; Tolerance_%: 10; VDC_V: 50; Value2: 50V; TaMin_C: -55; TaMax_C: 125; SizeArea_mm2: 1.28; SizeAreaWB_mm2: 4.68; SizeX_mm: 1.6; SizeY_mm: 0.8; SizeZ_mm: 1; AEC Category: Q200; Green_Lifecycle: Active; Green_REACh: Passed
C29 = C3216X7R2A105K160AA: CAP, CERM, 1 µF, 100 V,+/- 10%, X7R, 1206; Manufacturer: TDK; Polarized: N; CompType: Capacitor; Value: 1uF; U/M: EA; Cap_F: 0.000001; Tolerance_%: 10; ESR_ohm: 0.004575; Value1: 0.004575 ohm; VDC_V: 100; Value2: 100V; IRMS_A: 3.39639; TaMin_C: -55; TaMax_C: 125; Cap_Case: 1206; SizeArea_mm2: 5.12; SizeAreaWB_mm2: 10.92; SizeX_mm: 3.2; SizeY_mm: 1.6; SizeZ_mm: 1.8; AEC Category: Q200
C32 = GRM188R71H104KA93D: CAP, CERM, 0.1 µF, 50 V,+/- 10%, X7R, 0603; Manufacturer: MuRata; Polarized: N; CompType: Capacitor; Value: 0.1uF; U/M: EA; Cap_F: 0.0000001; Tolerance_%: 10; VDC_V: 50; Value2: 50V; TaMin_C: -55; TaMax_C: 125; SizeArea_mm2: 1.28; SizeAreaWB_mm2: 4.68; SizeX_mm: 1.6; SizeY_mm: 0.8; SizeZ_mm: 1; AEC Category: Q200; Green_Lifecycle: Active; Green_REACh: Passed
D1-D8 D12-D19 = BZT52C5V6T-7: Diode, Zener, 5.6 V, 300 mW, SOD-523; Manufacturer: Diodes Inc.; SymbolCreator: a0412235; U/M: EA; Power_W: 0.3; Vz_V: 5.6; Value1: 0.3W; RJA_CperW: 417; SizeAreaWB_mm2: 5.13; SizeArea_mm2: 1.53; SizeX_mm: 1.7; SizeY_mm: 0.9; SizeZ_mm: 0.65; AEC Category: Q101; Green_Lifecycle: Active; Green_REACh: Passed
D9 = BAT42WS-7-F: Diode, Schottky, 30 V, 0.2 A, SOD-323; Manufacturer: Diodes Inc.; U/M: EA; Vf_V: 1; Value: 30V; Value1: 0.2A; Value2: 1V; Io_A: 0.2; Vr_V: 30; SizeAreaWB_mm2: 8.695; SizeArea_mm2: 3.645; SizeX_mm: 2.7; SizeY_mm: 1.35; AEC Category: Q101; Green_Lifecycle: Not Set; Green_REACh: Incomplete
D10 = MMSZ4685T1G: Diode, Zener, 3.6 V, 500 mW, SOD-123; Manufacturer: ON Semiconductor; SymbolCreator: a0412235; U/M: EA; Power_W: 0.5; Vz_V: 3.6; Value1: 0.5W; RJA_CperW: 340; SizeAreaWB_mm2: 13.095; SizeArea_mm2: 6.545; SizeX_mm: 3.85; SizeY_mm: 1.7; SizeZ_mm: 1.35; AEC Category: Q101; Green_Lifecycle: Active; Green_REACh: Passed
D11 D20 = BAS516,115: Diode, Switching, 100 V, 0.25 A, SOD-523; Manufacturer: Nexperia; U/M: EA; Vf_V: 1.25; Value: 100V; Value1: 0.25A; Value2: 1.25V; Io_A: 0.25; Vr_V: 100; TJmax_C: 150; SizeAreaWB_mm2: 5.13; SizeArea_mm2: 1.53; SizeX_mm: 1.7; SizeY_mm: 0.9; SizeZ_mm: 0.65; AEC Category: Q101; Green_Lifecycle: Not Set; Green_REACh: Incomplete
Q1-Q16 = DMG2302UK-7: MOSFET, N-CH, 20 V, 2.8 A, AEC-Q101, SOT-23; Manufacturer: Diodes Inc.; Alternate Manufacturer: None; U/M: EA; ChType: N; Value: 20V; VdsMax_V: 20; Value1: 0.09 ohm; Rdson45_ohm: 0.09; Value2: 1.4 nC; QgTyp_nC: 1.4; Vgs_V: 12; IdsMax_A: 2.8; SizeAreaWB_mm2: 14; SizeArea_mm2: 7.5; SizeX_mm: 2.5; SizeY_mm: 3; SizeZ_mm: 1.1; AEC Category: Q101; AEC Qualified: Y; Green_Lifecycle: Active; Green_REACh: Passed; SymbolCreator: x0208325
Q17 = ZXMP10A13FTA: MOSFET, P-CH, -100 V, -0.6 A, SOT-23; Manufacturer: Diodes Inc.; Alternate Manufacturer: None; U/M: EA; ChType: P; Value: -100V; Value1: 1 ohm; Rdson45_ohm: 1; Value2: 3.5 nC; QgTyp_nC: 3.5; Vgs_V: -4; SizeAreaWB_mm2: 14; SizeArea_mm2: 7.5; SizeX_mm: 2.5; SizeY_mm: 3; SizeZ_mm: 1.1; AEC Category: Q101; Green_Lifecycle: Active; Green_REACh: Passed
Q18 = BSS123: MOSFET, N-CH, 100 V, 0.17 A, SOT-23; Manufacturer: Fairchild Semiconductor; Alternate Manufacturer: None; U/M: EA; ChType: N; Value: 100V; VdsMax_V: 100; Value1: 10 ohm; Rdson45_ohm: 10; Value2: 1.8 nC; QgTyp_nC: 1.8; Vgs_V: 20; IdsMax_A: 0.17; SizeAreaWB_mm2: 14; SizeArea_mm2: 7.5; SizeX_mm: 2.5; SizeY_mm: 3; SizeZ_mm: 1.1; AEC Category: Q101; Green_Lifecycle: Active; Green_REACh: Passed
Q19 = ZXTN25100BFHTA, Diodes Inc.: Transistor, NPN, 100 V, 3 A, AEC-Q101, SOT-23; CompType: BJT; PNP: 0; NPN: 1; Vceo_V: 100; Vcesat1_V: 0.07; Value: 100 V; IcRated_A: 3; Value1: 3 A; HfeMax: 300; TaMin_C: -55; TaMax_C: 150; SizeAreaWB_mm2: 14; SizeArea_mm2: 7.5; SizeX_mm: 2.5; SizeZ_mm: 1.1; U/M: EA; AEC Category: Q101; AEC Qualified: Y
R1-R16 R36-R43 R45 R72-R77 = CRCW120680R6FKEA: RES, 80.6, 1%, 0.25 W, 1206; Manufacturer: Vishay-Dale; CompType: Resistor; Value: 80.6; Value_Code: 80R6; Tolerance_%: 1; Power_W: 0.25; Value2: 0.25W; VDC_V: 200; TempCo: 100 ppm/C; SizeArea_mm2: 5.12; SizeX_mm: 3.2; SizeY_mm: 1.6; SizeZ_mm: 1.35; EIA_Code: E96; U/M: EA; AEC Category: Q200
R17 R19 R21 R23 R25 R27 R29 R31 R33 R52 R54 R56 R58 R60 R61 R79 R81 R83 R87 R88 R93 R95 R96 = CRCW0603100RFKEA: RES, 100, 1%, 0.1 W, 0603; Manufacturer: Vishay-Dale; CompType: Resistor; Value: 100; Value_Code: 100R; Tolerance_%: 1; Power_W: 0.1; Value2: 0.1W; VDC_V: 75; TempCo: 100 ppm/C; SizeArea_mm2: 1.28; SizeX_mm: 1.6; SizeY_mm: 0.8; EIA_Code: E96; U/M: EA; AEC Category: Q200; Green_Lifecycle: Active; Green_REACh: Passed
R18 R20 R22 R24 R26 R28 R30 R32 R51 R53 R55 R57 R59 R78 R80 R82 R84 R89 R90 = CRCW060310K0JNEA: RES, 10 k, 5%, 0.1 W, 0603; Manufacturer: Vishay-Dale; CompType: Resistor; Value: 10k; Res_ohm: 10000; Value_Code: 10k0; Tolerance_%: 5; Power_W: 0.1; Value2: 0.1W; VDC_V: 75; TempCo: 200 ppm/C; SizeArea_mm2: 1.28; SizeX_mm: 1.6; SizeY_mm: 0.8; SizeZ_mm: 1; EIA_Code: E24; U/M: EA; AEC Category: Q200; Green_Lifecycle: Active; Green_REACh: Passed
R34 R46 R47 R71 = CRCW04020000Z0ED: RES, 0, 5%, 0.063 W, 0402; Manufacturer: Vishay-Dale; CompType: Resistor; Value: 0; Value_Code: 0000; Tolerance_%: 5; Power_W: 0.063; Value2: 0.063W; VDC_V: 50; TempCo: 200 ppm/C; SizeArea_mm2: 0.5; SizeX_mm: 1; SizeZ_mm: 0.6; EIA_Code: E24; U/M: EA; AEC Category: Q200; Green_Lifecycle: Active; Green_REACh: Passed
R35 R48-R50 R62-R70 = CRCW06030000Z0EA: as R111 on sheet High level sch
R44 = CRCW120680R6FKEA: RES, 80.6, 1%, 0.25 W, 1206; Manufacturer: Vishay-Dale; CompType: Resistor; Value_Code: 80R6; Tolerance_%: 1; Power_W: 0.25; Value2: 0.25W; VDC_V: 200; TempCo: 100 ppm/C; SizeArea_mm2: 5.12; SizeX_mm: 3.2; SizeY_mm: 1.6; SizeZ_mm: 1.35; EIA_Code: E96; U/M: EA; AEC Category: Q200
R85 = RT0603DRE0713K3L: RES, 13.3 k, 0.5%, 0.1 W, 0603; Manufacturer: Yageo America; CompType: Resistor; Value: 13.3k; Res_ohm: 13300; Value_Code: 13k3; Tolerance_%: 0.5; Power_W: 0.1; Value2: 0.1W; VDC_V: 75; TempCo: 50 ppm/C; SizeArea_mm2: 1.28; SizeX_mm: 1.6; SizeY_mm: 0.8; SizeZ_mm: 1; EIA_Code: E192; U/M: EA; AEC Category: Q200
R86 = RT0603DRE07665KL: RES, 665 k, 0.5%, 0.1 W, 0603; Manufacturer: Yageo America; CompType: Resistor; Value: 665k; Res_ohm: 665000; Tolerance_%: 0.5; Power_W: 0.1; Value2: 0.1W; VDC_V: 75; TempCo: 50 ppm/C; SizeArea_mm2: 1.28; SizeX_mm: 1.6; SizeY_mm: 0.8; SizeZ_mm: 1; EIA_Code: E192; U/M: EA; AEC Category: Q200
R91 = CRCW06033M30JNEA: RES, 3.3 M, 5%, 0.1 W, 0603; Manufacturer: Vishay-Dale; CompType: Resistor; Value: 3.3Meg; Res_ohm: 3300000; Value_Code: 3M30; Tolerance_%: 5; Power_W: 0.1; Value2: 0.1W; VDC_V: 75; TempCo: 200 ppm/C; SizeArea_mm2: 1.28; SizeX_mm: 1.6; SizeY_mm: 0.8; SizeZ_mm: 1; EIA_Code: E24; U/M: EA; AEC Category: Q200; Green_Lifecycle: Active; Green_REACh: Passed
R92 = CRCW06031M00JNEA: RES, 1.0 M, 5%, 0.1 W, 0603; Manufacturer: Vishay-Dale; CompType: Resistor; Value: 1.0Meg; Res_ohm: 1000000; Value_Code: 1M00; Tolerance_%: 5; Power_W: 0.1; Value2: 0.1W; VDC_V: 75; TempCo: 200 ppm/C; SizeArea_mm2: 1.28; SizeX_mm: 1.6; SizeY_mm: 0.8; SizeZ_mm: 1; EIA_Code: E24; U/M: EA; AEC Category: Q200; Green_Lifecycle: Active; Green_REACh: Passed
R94 = RC0603FR-07249RL: RES, 249, 1%, 0.1 W, 0603; Manufacturer: Yageo America; CompType: Resistor; Value: 249; Value_Code: 249R; Tolerance_%: 1; Power_W: 0.1; Value2: 0.1W; VDC_V: 150; TempCo: 200 ppm/C; SizeArea_mm2: 1.28; SizeX_mm: 1.6; SizeY_mm: 0.8; EIA_Code: E96; U/M: EA; AEC Category: Q200; Green_Lifecycle: Active; Green_REACh: Passed
RT1-RT4 = 103AT-2: Thermistor NTC, 10.0k ohm, 1%, Disc, 5x8.4 mm; Manufacturer: Cantherm; Tolerance_%: 1; Power_W: 0.01; TaMin_C: -50; TaMax_C: 110; U/M: EA
S1 = RS-032G05A3-SM RT: Switch, Tactile, SPST-NO, 0.05A, 12V, SMD; Manufacturer: C&K Components; SymbolCreator: a0799628; VDC_V: 12; SwitchFunction: Off-Mom; PositionCount: 1; CurrentRating_mA: 50; Green_Lifecycle: Not Set; Green_REACh: Incomplete
U1 = CMP-0084230-1: Multicell Battery Monitor and Protection Family, PFB0048A (TQFP-48); Alternate PartNumber: bq76952PFBT; Alternate Manufacturer: Texas Instruments; SizeAreaWB_mm2: 121; SizeZ_mm: 1.2; SizeX_mm: 9; SizeArea_mm2: 81; CompType: IC; AEC Qualified: N; AEC Category: Q200

## Sheet Aux power.SchDoc
size 431 x 279 mm; Date: Not shown in title block; ApprovedBy: Not shown in title block; CheckedBy: Not shown in title block; Author: Not shown in title block; CompanyName: Not shown in title block; Engineer: Not shown in title block; Organization: Not shown in title block; Address1: Not shown in title block; Address2: Not shown in title block; Address3: Not shown in title block; Address4: Not shown in title block; DocumentNumber: 1; Revision: Use project parameter SCH_Rev; SheetNumber: 5; SheetTotal: 7; PageSetup: Record=PageOptions¦CenterHorizontal=True¦CenterVertical=True¦PrintScale=1.00¦XCorrection=1.00¦YCorrection=1.00¦PrintKind=0¦BorderSize=5000000¦LeftOffset=0¦BottomOffset=0¦Orientation=2¦PaperLength=1000¦PaperWidth=1000¦Scale=100¦PaperSource=15¦PrintQuality=600¦MediaType=1¦DitherType=10¦PaperKind=Letter¦PrintScaleMode=1
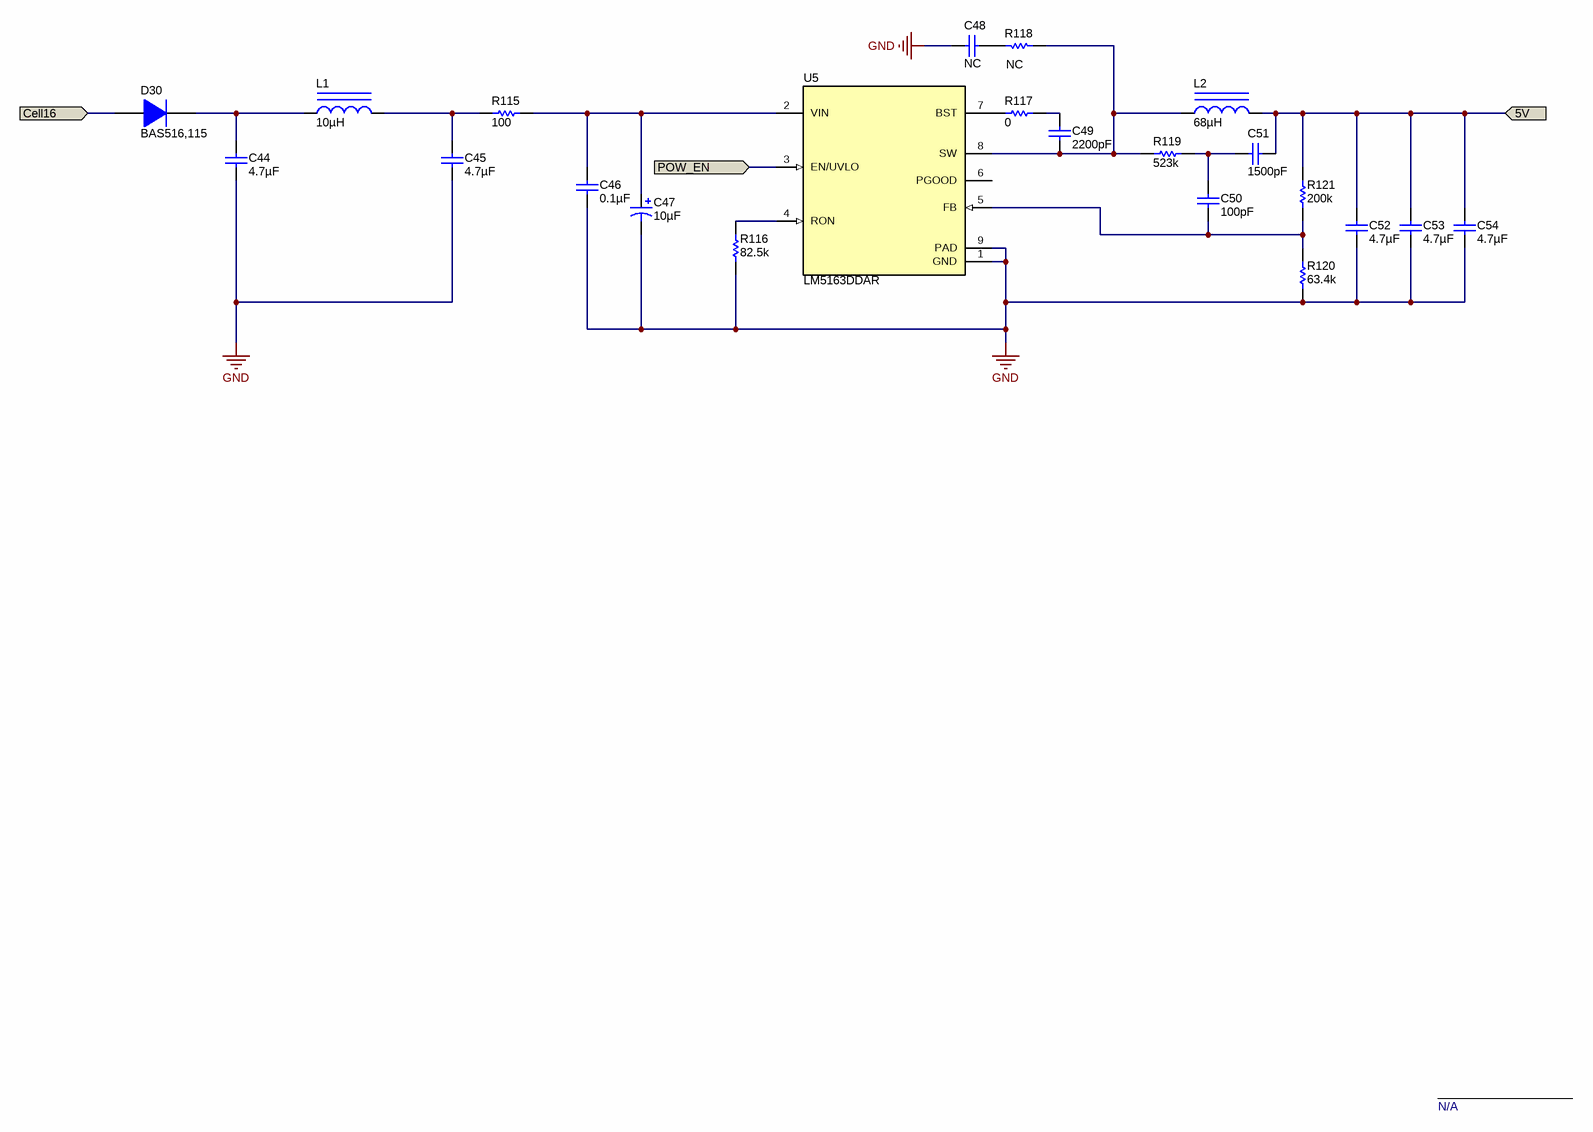
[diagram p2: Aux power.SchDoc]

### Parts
C44  ValueDisplayed: 4.7µF  [1210]  (hidden comment: C3225X7S2A475K200AE)
C45  ValueDisplayed: 4.7µF  [1210]  (hidden comment: C3225X7S2A475K200AE)
C46  ValueDisplayed: 0.1µF  [0603]  (hidden comment: GRM188R72A104KA35D)
C47  ValueDisplayed: 10µF  [UUX_800x620]  (hidden comment: UUX2A100MNL1GS)
C48  ValueDisplayed: NC  [0603]  (hidden comment: GRM1885C1H560JA01D)
C49  ValueDisplayed: 2200pF  [0402]  (hidden comment: GRM155R71H222KA01D)
C50  ValueDisplayed: 100pF  [0603]  (hidden comment: GRM1885C1H101JA01D)
C51  ValueDisplayed: 1500pF  [0402]  (hidden comment: GRM155R71H152KA01D)
C52  ValueDisplayed: 4.7µF  [0805_HV]  (hidden comment: GRM21BR71C475KA73L)
C53  ValueDisplayed: 4.7µF  [0805_HV]  (hidden comment: GRM21BR71C475KA73L)
C54  ValueDisplayed: 4.7µF  [0805_HV]  (hidden comment: GRM21BR71C475KA73L)
D30  BAS516,115  [SOD-523]
L1  ValueDisplayed: 10µH  [WE-MAPI_3015]  (hidden comment: 74438335010)
L2  ValueDisplayed: 68µH  [WE-PD_7345]  (hidden comment: 744777168)
R115  ValueDisplayed: 100  [0603]  (hidden comment: CRCW0603100RFKEA)
R116  ValueDisplayed: 82.5k  [0603]  (hidden comment: CRCW060382K5FKEA)
R117  ValueDisplayed: 0  [0402]  (hidden comment: CRCW04020000Z0ED)
R118  ValueDisplayed: NC  [0603]  (hidden comment: RC0603FR-07499KL)
R119  ValueDisplayed: 523k  [0402]  (hidden comment: RC0402FR-07523KL)
R120  ValueDisplayed: 63.4k  [0603]  (hidden comment: CRCW060363K4FKEA)
R121  ValueDisplayed: 200k  [0603]  (hidden comment: CRCW0603200KFKEA)
U5  LM5163DDAR  [DDA0008E_M]

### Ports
5V, Cell16 (in), POW_EN (in)

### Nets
GND: C44.2 C45.2 C46.2 C47.2(-) C48.2 C52.2 C53.2 C54.2 R116.1 R120.1 U5.1(GND) U5.9(PAD)
5V: C51.1 C52.1 C53.1 C54.1 L2.2 R121.2 ; port 5V
Cell16: D30.2(A) ; port Cell16
POW_EN: U5.3(EN/UVLO) ; port POW_EN
NetC44_1: C44.1 D30.1(K) L1.1
NetC45_1: C45.1 L1.2 R115.1
NetC46_1: C46.1 C47.1(+) R115.2 U5.2(VIN)
NetC48_1: C48.1 R118.1
NetC49_1: C49.1 R117.2
NetC49_2: C49.2 L2.1 R118.2 R119.1 U5.8(SW)
NetC50_1: C50.1 C51.2 R119.2
NetC50_2: C50.2 R120.2 R121.1 U5.5(FB)
NetR116_2: R116.2 U5.4(RON)
NetR117_1: R117.1 U5.7(BST)

Not connected (* = marked no-connect by the designer): U5 6(PGOOD)

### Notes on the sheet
- N/A

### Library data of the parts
C44 C45 = C3225X7S2A475K200AE: CAP, CERM, 4.7 µF, 100 V,+/- 10%, X7S, 1210; Manufacturer: TDK; Polarized: N; CompType: Capacitor; Value: 4.7uF; U/M: EA; Cap_F: 0.0000047; Tolerance_%: 10; VDC_V: 100; Value2: 100V; TaMin_C: -55; TaMax_C: 125; SizeArea_mm2: 8; SizeAreaWB_mm2: 14.7; SizeX_mm: 3.2; SizeY_mm: 2.5; SizeZ_mm: 1.35; AEC Category: Q200; Green_Lifecycle: Active; Green_REACh: Passed
C46 = GRM188R72A104KA35D: CAP, CERM, 0.1 µF, 100 V,+/- 10%, X7R, 0603; Manufacturer: MuRata; Polarized: N; CompType: Capacitor; Value: 0.1uF; U/M: EA; Cap_F: 0.0000001; Tolerance_%: 10; VDC_V: 100; Value2: 100V; TaMin_C: -55; TaMax_C: 125; SizeArea_mm2: 1.28; SizeAreaWB_mm2: 4.68; SizeX_mm: 1.6; SizeY_mm: 0.8; SizeZ_mm: 1; AEC Category: Q200; Green_Lifecycle: Active; Green_REACh: Passed
C47 = UUX2A4R7MCL1GS: CAP, AL, 10 µF, 100 V, +/- 20%, SMD; Manufacturer: Nichicon; Polarized: Y; CompType: Capacitor; Value: 10uF; U/M: EA; Cap_F: 0.0000047; Tolerance_%: 20; VDC_V: 100; Value2: 100V; IRMS_A: 0.042; TaMin_C: -55; TaMax_C: 105; Cap_Case: 8x6.2mm; SizeAreaWB_mm2: 106.09; SizeArea_mm2: 68.89; SizeX_mm: 8.3; SizeZ_mm: 6.5; AEC Category: Q200; AEC Qualified: N
C48 = GRM1885C1H560JA01D: CAP, CERM, 56 pF, 50 V,+/- 5%, C0G/NP0, 0603; Manufacturer: MuRata; Polarized: N; CompType: Capacitor; Value: 56pF; U/M: EA; Cap_F: 0.000000000056; Tolerance_%: 5; VDC_V: 50; Value2: 50V; TaMin_C: -55; TaMax_C: 125; SizeArea_mm2: 1.28; SizeAreaWB_mm2: 4.68; SizeX_mm: 1.6; SizeY_mm: 0.8; SizeZ_mm: 1; AEC Category: Q200; Green_Lifecycle: Active; Green_REACh: Passed
C49 = GRM155R71H222KA01D: CAP, CERM, 2200 pF, 50 V,+/- 10%, X7R, 0402; Manufacturer: MuRata; Polarized: N; CompType: Capacitor; Value: 2200pF; U/M: EA; Cap_F: 0.0000000022; Tolerance_%: 10; VDC_V: 50; Value2: 50V; TaMin_C: -55; TaMax_C: 125; SizeArea_mm2: 0.5; SizeAreaWB_mm2: 3; SizeX_mm: 1; SizeZ_mm: 0.6; AEC Category: Q200; Green_Lifecycle: Active; Green_REACh: Passed
C50 = GRM1885C1H101JA01D: CAP, CERM, 100 pF, 50 V,+/- 5%, C0G/NP0, 0603; Manufacturer: MuRata; Polarized: N; CompType: Capacitor; Value: 100pF; U/M: EA; Cap_F: 0.0000000001; Tolerance_%: 5; VDC_V: 50; Value2: 50V; TaMin_C: -55; TaMax_C: 125; SizeArea_mm2: 1.28; SizeAreaWB_mm2: 4.68; SizeX_mm: 1.6; SizeY_mm: 0.8; SizeZ_mm: 1; AEC Category: Q200; Green_Lifecycle: Active; Green_REACh: Passed
C51 = GRM155R71H152KA01D: CAP, CERM, 1500 pF, 50 V,+/- 10%, X7R, 0402; Manufacturer: MuRata; Polarized: N; CompType: Capacitor; Value: 1500pF; U/M: EA; Cap_F: 0.0000000015; Tolerance_%: 10; VDC_V: 50; Value2: 50V; TaMin_C: -55; TaMax_C: 125; SizeArea_mm2: 0.5; SizeAreaWB_mm2: 3; SizeX_mm: 1; SizeZ_mm: 0.6; AEC Category: Q200
C52-C54 = GRM21BR71C475KA73L: CAP, CERM, 4.7 µF, 16 V,+/- 10%, X7R, 0805; Manufacturer: MuRata; Polarized: N; CompType: Capacitor; Value: 4.7uF; U/M: EA; Cap_F: 0.0000047; Tolerance_%: 10; ESR_ohm: 0.006; Value1: 0.006 ohm; VDC_V: 16; Value2: 16V; TaMin_C: -55; TaMax_C: 125; Cap_Case: 0805; SizeArea_mm2: 2.5; SizeAreaWB_mm2: 6.75; SizeX_mm: 2; SizeY_mm: 1.25; SizeZ_mm: 1.45; AEC Category: Q200; Green_Lifecycle: Active; Green_REACh: Passed
D30 = BAS516,115: as D11 on sheet Monitor and Cell balancing
L1 = 74438335010: Inductor, Shielded, 1 µH, 2.7 A, 0.039 ohm, SMD; Manufacturer: Wurth Elektronik; Value: 1uH; Ind_H: 1.0E-6; Imax_A: 2.7; Irms: 2.7A @ 40C rise; Isat: 4.5A @ 20% inductance drop; DCR_ohm: 0.039; Value2: 2.7A; SizeAreaWB_mm2: 16; SizeArea_mm2: 9; SizeX_mm: 3; SizeZ_mm: 1.2; AEC Category: Q200; Green_Lifecycle: Active; Green_REACh: Passed
L2 = 744777168: Inductor, Shielded Drum Core, Metal Composite, 68 µH, 0.87 A, 0.239 ohm, SMD; Manufacturer: Wurth Elektronik; Value: 68uH; Ind_H: 68.0E-6; Imax_A: 0.87; Irms: 0.87A @ 40C rise; Isat: 0.95A @ 10% inductance drop; DCR_ohm: 0.239; Value2: 0.87A; SizeAreaWB_mm2: 86.49; SizeArea_mm2: 53.29; SizeX_mm: 7.3; SizeZ_mm: 4.5; AEC Category: Q200; Green_Lifecycle: Active; Green_REACh: Passed
R115 = CRCW0603100RFKEA: as R17 on sheet Monitor and Cell balancing
R116 = CRCW060382K5FKEA: RES, 82.5 k, 1%, 0.1 W, 0603; Manufacturer: Vishay-Dale; CompType: Resistor; Value: 82.5k; Res_ohm: 82500; Value_Code: 82k5; Tolerance_%: 1; Power_W: 0.1; Value2: 0.1W; VDC_V: 75; TempCo: 100 ppm/C; SizeArea_mm2: 1.28; SizeX_mm: 1.6; SizeY_mm: 0.8; EIA_Code: E96; U/M: EA; AEC Category: Q200; Green_Lifecycle: Active; Green_REACh: Passed
R117 = CRCW04020000Z0ED: as R34 on sheet Monitor and Cell balancing
R118 = RC0603FR-07499KL: RES, 499 k, 1%, 0.1 W, 0603; Manufacturer: Yageo America; CompType: Resistor; Value: 499k; Res_ohm: 499000; Tolerance_%: 1; Power_W: 0.1; Value2: 0.1W; VDC_V: 150; TempCo: 200 ppm/C; SizeArea_mm2: 1.28; SizeX_mm: 1.6; SizeY_mm: 0.8; EIA_Code: E96; U/M: EA; AEC Category: Q200; Green_Lifecycle: Active; Green_REACh: Passed
R119 = CRCW0402523KFKED: RES, 523 k, 1%, 0.063 W, 0402; Manufacturer: Yageo; CompType: Resistor; Value: 523k; Res_ohm: 523000; Tolerance_%: 1; Power_W: 0.063; Value2: 0.063W; VDC_V: 50; TempCo: 100 ppm/C; SizeArea_mm2: 0.5; SizeZ_mm: 0.6; EIA_Code: E96; U/M: EA; AEC Category: Q200
R120 = CRCW060363K4FKEA: RES, 63.4 k, 1%, 0.1 W, 0603; Manufacturer: Vishay-Dale; CompType: Resistor; Value: 63.4k; Res_ohm: 63400; Value_Code: 63k4; Tolerance_%: 1; Power_W: 0.1; Value2: 0.1W; VDC_V: 75; TempCo: 100 ppm/C; SizeArea_mm2: 1.28; SizeX_mm: 1.6; SizeY_mm: 0.8; EIA_Code: E96; U/M: EA; AEC Category: Q200
R121 = CRCW0603200KFKEA: RES, 200 k, 1%, 0.1 W, 0603; Manufacturer: Vishay-Dale; CompType: Resistor; Value: 200k; Res_ohm: 200000; Tolerance_%: 1; Power_W: 0.1; Value2: 0.1W; VDC_V: 75; TempCo: 100 ppm/C; SizeArea_mm2: 1.28; SizeX_mm: 1.6; SizeY_mm: 0.8; EIA_Code: E96; U/M: EA; AEC Category: Q200; Green_Lifecycle: Active; Green_REACh: Passed
U5 = CMP-0861029-1: 100-V Input, 0.5-A Synchronous Buck DC/DC Converter with Ultra-low IQ, DDA0008E (HSOIC-8); Alternate Manufacturer: Texas Instruments; SizeAreaWB_mm2: 55.2; SizeZ_mm: 1.7; SizeX_mm: 6; AEC Qualified: N; AEC Category: Q200; SizeArea_mm2: 29.4; CompType: IC; SizeY_mm: 4.9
